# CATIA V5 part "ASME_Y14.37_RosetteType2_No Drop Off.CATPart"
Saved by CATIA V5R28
Part number: 333X3333-303
Revision: --
Nomenclature: ASME_Y14.37_RosetteType2
Bounding box of the stored display mesh (mm): x -188.298 to 149.724, y -714.612 to 664.697, z 0 to 93.98
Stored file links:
  C:\Users\jvl2147\Documents\AP242 testing\Composite Example Parts for PER\No Drop Off Zone\ASME_Y14.37_RosetteType2_No Drop Off.CATPart
  \\NW\Data\MSE-Composites\ASME Y14.37\ASME Y-14.37_COMPOSITES.CATMaterial
  C:\Program Files\Dassault Systemes\B28SP3PRALL\win_b64\startup\composites\LaminateColors.txt
  C:\Program Files\Dassault Systemes\B28SP3PRALL\win_b64\startup\composites\DropOffPattern1BackSlash.txt
  C:\Program Files\Dassault Systemes\B28SP3PRALL\win_b64\startup\composites\DropOffPattern1Backslash.txt
  C:\Program Files\Dassault Systemes\B28SP3PRALL\win_b64\startup\composites\DropOffPattern1InverseV.txt
  C:\Program Files\Dassault Systemes\B28SP3PRALL\win_b64\startup\composites\DropOffPattern1InverseW.txt
  C:\Program Files\Dassault Systemes\B28SP3PRALL\win_b64\startup\composites\DropOffPattern1Slash.txt
  C:\Program Files\Dassault Systemes\B28SP3PRALL\win_b64\startup\composites\DropOffPattern1V.txt
  C:\Program Files\Dassault Systemes\B28SP3PRALL\win_b64\startup\composites\DropOffPattern1V_Symetry.txt
  C:\Program Files\Dassault Systemes\B28SP3PRALL\win_b64\startup\composites\DropOffPattern1V_Symetry_2Consecutive.txt
  C:\Program Files\Dassault Systemes\B28SP3PRALL\win_b64\startup\composites\DropOffPattern1W.txt
  C:\Program Files\Dassault Systemes\B28SP3PRALL\win_b64\startup\composites\DropOffPattern2Cross.txt
  C:\Program Files\Dassault Systemes\B28SP3PRALL\win_b64\startup\composites\DropOffPattern2Diamond.txt
  C:\Program Files\Dassault Systemes\B28SP3PRALL\win_b64\startup\composites\DropOffPattern2Socks.txt
  C:\Program Files\Dassault Systemes\B28SP3PRALL\win_b64\startup\composites\DropOffPattern45AfterOthers.txt
  C:\Program Files\Dassault Systemes\B28SP3PRALL\win_b64\startup\composites\DropOffPattern4TwinDiamonds45.txt
  C:\Program Files\Dassault Systemes\B28SP3PRALL\win_b64\startup\composites\DropOffPattern5Cross_Pseudo_Sym.txt
  C:\Program Files\Dassault Systemes\B28SP3PRALL\win_b64\startup\composites\DropOffPattern5Diamond_Pseudo_Sym.txt
  C:\Program Files\Dassault Systemes\B28SP3PRALL\win_b64\startup\composites\DropOffPattern5Socks_Pseudo_Sym.txt
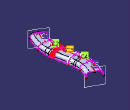
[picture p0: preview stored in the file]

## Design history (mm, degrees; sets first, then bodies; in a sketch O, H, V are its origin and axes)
AxisSystem1 "ROSETTE COORDINATE SYSTEM": origin (-72.9205, -637.9645, 93.98), X (0.5026, 0.8645, 0), Y (-0.8645, 0.5026, 0), Z (0, 0, 1)
CompParametersFeature1 "CATCoParametersFeatName": Value 0, Value 45, Value -45, Value 90
CompEOPGroupFeature1 "CATCoEOPGroupFeatName"
TTRSSet1
CompGridRoot1
CompStacking1 "Stacking"
Set1 "CONSTRUCTION GEOMETRY"
  Set2 "CONSTRUCTION - LAMINATE REFERENCE SURFACE"
    Sketch1 on xy-plane, origin (0, 0, 0), H (1, 0, 0), V (0, 1, 0)
      spline S1 through (-79.505, -649.09) (21.2912, -260.3998) (-51.6257, 228.8061) (37.963, 602.845)
    Plane1: type Normal, Curve Sketch1, RefPoint vertex of Sketch1, Ratio 0
    Sketch2 on Plane1, origin (-464.3095, -417.3341, 0), H (-0.8566, 0.5159, 0), V (0, 0, 1)
      line L1 (-525.4052, 91.6386) -> (-373.0052, 91.6386)
      line L2 (-322.2052, 40.8386) -> (-322.2052, 0)
      line L3 (-576.2052, 0) -> (-576.2052, 40.8386)
      reference projected point E1 (-449.2052, 0) from vertex of Sketch1
      reference projected point E2 (-449.2052, 0) from vertex of Sketch1
      arc A1 centre (-373.0052, 40.8386) radius 50.8 from (-373.0052, 91.6386) to (-322.2052, 40.8386) cw
      arc A2 centre (-525.4052, 40.8386) radius 50.8 from (-576.2052, 40.8386) to (-525.4052, 91.6386) cw
      distance E1 L2 = 127
      distance E2 L3 = 127
      radius A1 = 50.8
      radius A2 = 50.8
      horizontal: L1 H
      vertical: L2 V, L3 V
      tangency: A1 L1, A1 L2, A2 L3, A2 L1
    Sweep1: type Unspec, Profile Sketch2, Guide Sketch1
  Set3 "CONSTRUCTION - PLIES EOPS"
    Plane2: type Normal, Curve Sketch1, RefPoint vertex of Sketch1, Ratio 0
    Plane3: type Normal, Curve Sketch1, RefPoint {point type OnCurve, Support Sketch1, Length 1118.262}, Ratio 0.99
    Plane4: type Normal, Curve Sketch1, Ratio 0.01
    Intersect1: ToIntersect1 Plane3, ToIntersect2 Sweep1
    Intersect2: ToIntersect1 Sweep1, ToIntersect2 Plane4
    Plane5: type Offset, RefPlane xy-plane, Offset 2.54
    Intersect3: ToIntersect1 Plane5, ToIntersect2 Join1
    Near1: MultiElement Intersect3, ReferenceElement edge of Sweep1
    Near2: MultiElement Intersect3, ReferenceElement edge of Sweep1
    CurvePar1: Offset2 0, Offset1 50, Support Join1
  Set4 "CONSTRUCTION - ROSETTE COORDINATE SYSTEM"
    Intersect4: ToIntersect1 Plane4, ToIntersect2 Project1
    Line1: type Tangency, RefPoint Intersect4, Curve Project1, Start 0, End 25.4
    Plane6: type Offset, RefPlane xy-plane, Offset 93.98
    Project1 "CURVE": ToProject Sketch1, Support Plane6
  CurvePar2: Offset Near1, Support Join1, Offset2 0, Offset1 50.8
  Set5 "CONSTRUCTION - GRID"
    Point1: type OnCurve, Support Project2, Length 258.5616 {= length(Project2) / 5}
    Plane7: type Normal, Curve Project2, RefPoint Point1
    Point2: type OnCurve, Support Project2, Length 517.1231 {= (length(Project2)) * 2 / 5}
    Plane8: type Normal, Curve Project2, RefPoint Point2
    Point3: type OnCurve, Support Project2, Length 775.6847 {= (length(Project2)) * 3 / 5}
    Plane9: type Normal, Curve Project2, RefPoint Point3
    Point4: type OnCurve, Support Project2, Length 1034.2463 {= (length(Project2)) * 4 / 5}
    Plane10: type Normal, Curve Project2, RefPoint Point4
    Plane11: type Normal, Curve Sketch1, Ratio 0.01
    Plane12: type Normal, Curve Sketch1, RefPoint {point type OnCurve, Support Sketch1, Length 1118.262}, Ratio 0.99
    Sweep2: type Segment, GuideCrv Near1, Length1 10, Length2 10, Angle 90, GuideSurf Join1
    Sweep3: type Segment, GuideCrv Near2, GuideSurf Join1, Length1 10, Length2 10, Angle 90
    CurvePar3: Offset2 0, Offset1 20, Support Join1
    CurvePar4: Offset2 0, Offset1 1, Support Join1
    CurvePar5: Support Join1, Offset2 0, Offset1 1
Set6 "ENGINEERING GEOMETRY"
  Set7 "LAMINATE REFERENCE SURFACE"
    Join1 "LAMINATE REFERENCE SURFACE": Elements Sweep1
  Set8 "GUIDE CURVE - ZERO DEGREE ORIENTATION"
    Project2 "0° GUIDE CURVE": ToProject Sketch1, Support Join1, Direction xy-plane
  Set9 "LLAI - NO DROP OFF ZONE"
    CompStdContourFeature1 "LLAI - NO DROP OFF ZONE BOUNDARY 1": ClosedSetOfCurves (CurvePar4; {curvepar Support Join1, Offset2 0, Offset1 20}; CurvePar5; CurvePar3), ExtrapolDist 0.2, SupportSurface Join1
    CompGridNoDropOffArea1 "LLAI - NO DROP OFF ZONE 1": NoDropOffContour CompStdContourFeature1
    CompStdContourFeature2 "LLAI - NO DROP OFF ZONE BOUNDARY 2": ClosedSetOfCurves (CurvePar1; CurvePar4; CurvePar5), ExtrapolDist 0.2, SupportSurface Join1
    CompGridNoDropOffArea2 "LLAI - NO DROP OFF ZONE 2": NoDropOffContour CompStdContourFeature2
Set10 "Top Surface from Virtual Stackings"
  CompIsoThickAreasTopSurface1 "CATCoIsoThickAreasTopSurfaceFeatName": ListITAs ({datumsurface}; {datumsurface}; {datumsurface}; {datumsurface}; {datumsurface}), ListRampContours ({datumcurve}; {datumcurve}; {datumcurve}; {datumcurve})
Body1 "-303" (main body)
  ThickSurface1: BotOffset 0, Surface CompIsoThickAreasTopSurface1, TopOffset 2
  Split1: SplitPlane Join1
